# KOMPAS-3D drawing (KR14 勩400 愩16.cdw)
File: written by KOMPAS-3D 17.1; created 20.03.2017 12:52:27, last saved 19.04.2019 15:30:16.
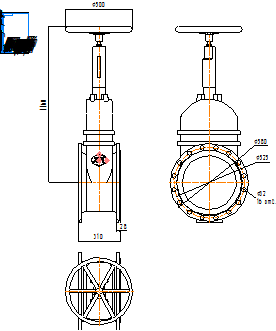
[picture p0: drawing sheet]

Sheet 1: A4, portrait

Title block, sheet 1: name: KR14 Ду400 Ру16; material: Внимание! Данный продукт является объектом авторского права ООО «Торговый Дом АДЛ». / Запрещается изменение, копирование, распространение / (в том числе путем копирования на другие сайты и ресурсы в Интернете) / или любое иное использование информации и объектов без предварительного / согласия правообладателя (ООО «Торговый Дом АДЛ»).; mass: 508; sheets: 1; organisation: ООО "Торговый дом АДЛ"; sheet format: A4; stored path: C:\Users\kka\KOMPAS_Work\!Trash\Задвижки ГРАНАР с приводами\KR14 Ду350 Ру16.cdw

Views: Вид 1, Проекционный вид 2, Проекционный вид 3
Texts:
  Klimkovich
  ADL
Dimensions and other numbers on the sheet: 500; 1160; 580; 525; 32; 16 отв.; 310; 28; 1:1; 1; 508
